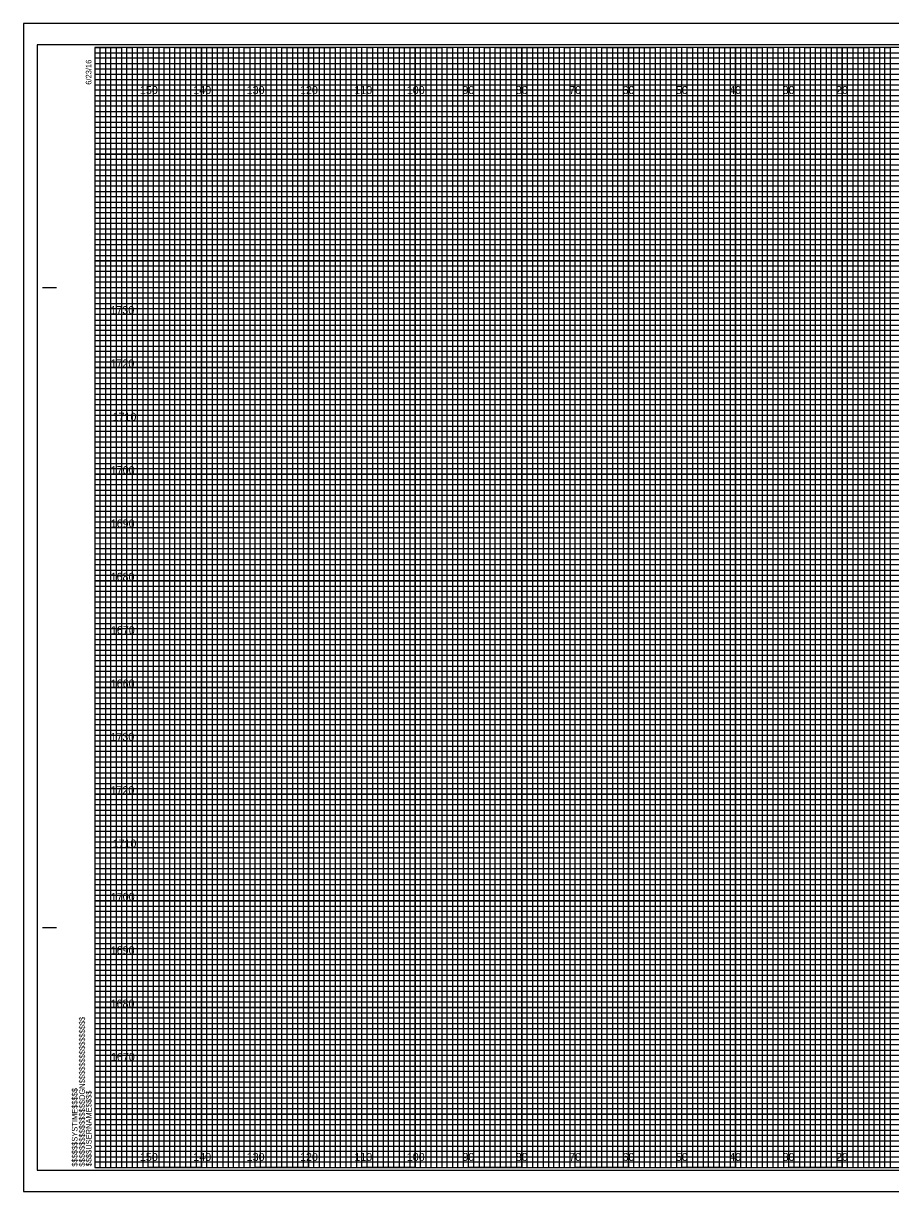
# Model space of a CAD drawing. Extents: x -13 to 323, y -5 to 6154.
# Drawn here: x -13.4 to 149.1, y -4.5 to 214.5 of the extents above; entities that cross this region are included whole.
import ezdxf

# ---------------------------------------------------------------- set-up
doc = ezdxf.new("R2010")
doc.units = 0
for name, color, linetype in [('Prop Retaining Wall', 7, 'Continuous'), ('Prop XS Alignment Label', 7, 'Continuous'), ('Prop XS DDE', 7, 'Continuous'), ('Prop XS DDE Elevations', 7, 'Continuous'), ('Prop XS DDE Slope Text', 7, 'Continuous'), ('Prop XS Earthwork Shape', 7, 'Continuous'), ('Prop XS Elevation Labels', 7, 'Continuous'), ('Prop XS Station Labels', 7, 'Continuous'), ('Raster_Level_0', 7, 'Continuous'), ('Scratch_Level_3', 7, 'Continuous'), ('Sheet Cutting Line CELL', 7, 'Continuous')]:
    doc.layers.add(name, color=color, linetype=linetype)

msp = doc.modelspace()

# ---------------------------------------------------------------- linework, layer by layer
at = {"layer": 'Prop Retaining Wall'}
for p, q in [((0, 209), (260, 209)), ((260, 207.98), (0, 207.98)), ((0, 207.98), (0, 207)), ((0, 207), (260, 207)), ((260, 205.89), (0, 205.89)), ((0, 205.89), (0, 204)), ((0, 204), (320, 204))]:
    msp.add_line(p, q, dxfattribs=at)
for points in [[(0, 203), (270, 203), (320, 203), (320, 202), (0, 202)], [(0, 201), (320, 201), (320, 199), (0, 199)], [(0, 198), (320, 198), (320, 197), (0, 196.98)], [(0, 196), (320, 196), (320, 194), (0, 194)], [(0, 193), (320, 193), (320, 192), (0, 192)], [(0, 191), (320, 191), (320, 189), (0, 189)], [(0, 188), (320, 188), (320, 187), (0, 187)], [(0, 186), (320, 186), (320, 184), (0, 184)], [(0, 183), (320, 183), (320, 182), (0, 182)], [(0, 181), (320, 181), (320, 179), (0, 179)], [(0, 178), (320, 178), (320, 177), (0, 177)], [(0, 176), (320, 176), (320, 173.95), (320, 173), (320, 172), (0, 172)], [(0, 174), (320, 174), (320, 173), (0, 173)], [(0, 171), (320, 171), (320, 169), (0, 169.03)], [(0, 169.03), (320, 169), (320, 168), (0, 168)], [(0, 167), (320, 167), (320, 166), (0, 166)], [(0, 164), (320, 164), (320, 163), (0, 163)], [(0, 162), (320, 162), (320, 161), (0, 161)], [(-0.07, 158.89), (320, 158.89), (320, 157.88), (-0.07, 157.88)], [(0, 157), (320, 157), (320, 156), (0, 156)], [(0, 154), (320, 154), (320, 153), (0, 153)], [(0, 152), (320, 152), (320, 151), (0, 151)], [(0, 149), (320, 149), (320, 148), (0, 148)], [(0, 147), (320, 147), (320, 146), (0, 146)], [(0, 144), (320, 144), (320, 143), (0, 143)], [(0, 142), (320, 142), (320, 141), (0, 141)], [(0, 139), (320, 139), (319.99, 137.98), (0, 138)], [(0, 137), (320, 137), (320, 136), (0, 136)], [(0, 134), (320, 134), (320, 133), (0, 133)], [(0, 132), (320, 132), (320, 131), (0, 131)], [(0, 129), (320, 129), (320, 128), (0, 128)], [(0, 127), (320, 127), (320, 126), (0, 126)], [(0, 124), (320, 124), (320, 123), (0, 123)], [(0, 122), (320, 122), (320, 121), (0, 121)], [(0, 119), (320, 119), (320, 118), (0, 118)], [(0, 116.99), (320.07, 116.91), (320, 116), (0, 116)], [(0, 114), (320, 114), (320, 113), (0, 113)], [(0, 112), (320, 112), (320, 111), (0, 111)], [(0, 109), (320, 109), (320, 108), (0, 108)], [(0, 107), (320, 107), (320, 106), (0, 106)], [(0, 104), (320, 104), (320, 103), (0, 103)], [(0, 102), (320, 102), (320, 101), (0, 101)], [(0, 99), (320, 99), (320, 98), (0, 98)], [(0, 97), (320, 97), (320, 96), (0, 96)], [(0, 94), (320, 94), (320, 93), (0, 93)], [(0, 92), (320, 92), (320, 91), (0, 91)], [(0, 89), (320, 89), (320, 88), (0, 88)], [(0, 87), (320, 87), (320, 86), (0, 86)], [(0, 84), (320, 84), (320, 83), (0, 83)], [(0, 82), (320, 82), (320, 81), (0, 81)], [(0, 79), (320, 79), (319.99, 77.98), (0, 78)], [(0, 77), (320, 77), (320, 76), (0, 76)], [(0, 74), (320, 74), (320, 73), (0, 73)], [(0, 72), (320, 72), (320, 71), (0, 71)], [(0, 69), (320, 69), (320, 68), (0, 68)], [(0, 67), (320, 67), (320, 66), (0, 66)], [(0, 64), (320, 64), (320, 63), (0, 63)], [(0, 62), (320, 62), (320, 61), (0, 61)], [(0, 59), (320, 59), (320, 58), (0, 58)], [(0, 56.99), (320.07, 56.91), (320, 56), (0, 56)], [(0, 54), (320, 54), (320, 53), (0, 53)], [(0, 52), (320, 52), (320, 51), (0, 51)], [(0, 49), (320, 49), (320, 48), (0, 48)], [(0, 47), (320, 47), (320, 46), (0, 46)], [(0, 44), (320, 44), (320, 43), (0, 43)], [(0, 42), (320, 42), (320, 41), (0, 41)], [(0, 39), (320, 39), (320, 38), (0, 38)], [(0, 37), (320, 37), (320, 36), (0, 36)], [(0, 34), (320, 34), (320, 33), (0, 33)], [(0, 32), (320, 32), (320, 31), (0, 31)], [(0, 29), (320, 29), (320, 28), (0, 28)], [(0, 27), (320, 27), (320, 26), (0, 26)], [(0, 24), (320, 24), (320, 23), (0, 23)], [(0, 22), (320, 22), (320, 21), (0, 21)], [(0, 19), (320, 19), (320, 18), (0, 18)], [(0, 17), (320, 17), (320, 16), (0, 16)], [(0, 14), (320, 14), (320, 13), (0, 13)], [(0, 12), (320, 12), (320, 11), (0, 11)], [(0, 9), (320, 9), (320, 8), (0, 8)], [(0, 7), (320, 7), (320, 6), (0, 6)], [(0, 4), (320, 4), (320, 3), (0, 3)], [(0, 2), (320, 2), (320, 1), (0, 1)]]:
    msp.add_lwpolyline(points, dxfattribs=at)
at = {"layer": 'Prop XS Alignment Label'}
for p, q in [((-9.8, 165), (-7.3, 165)), ((-9.7, 165), (-7.2, 165)), ((-9.8, 45), (-7.3, 45)), ((-9.7, 45), (-7.2, 45)), ((0, 0), (0, 0)), ((0, 0), (0, 0)), ((0, 0), (0, 0)), ((0, 0), (0, 0)), ((0, 0), (0, 0)), ((0, 0), (0, 0)), ((0, 0), (0, 0))]:
    msp.add_line(p, q, dxfattribs=at)
msp.add_lwpolyline([(320, 210), (0, 210), (0, 0), (320, 0)], close=True, dxfattribs=at)
at = {"layer": 'Prop XS DDE'}
msp.add_lwpolyline([(-13.4, -4.5), (323.3, -4.5), (323.3, 214.5), (-13.4, 214.5)], close=True, dxfattribs=at)
at = {"layer": 'Prop XS DDE Elevations'}
for p, q in [((10, 0), (10, 210)), ((20, 0), (20, 210)), ((30, 0), (30, 210)), ((40, 0), (40, 210)), ((50, 0), (50, 210)), ((60, 0), (60, 210)), ((70, 0), (70, 210)), ((80, 0), (80, 210)), ((90, 0), (90, 210)), ((100, 0), (100, 210)), ((110, 0), (110, 210)), ((120, 0), (120, 210)), ((130, 0), (130, 210)), ((140, 0), (140, 210)), ((0, 200), (320, 200)), ((0, 190), (320, 190)), ((0, 180), (320, 180)), ((0, 170), (320, 170)), ((0, 160), (320, 160)), ((0, 150), (320, 150)), ((0, 140), (320, 140)), ((0, 130), (320, 130)), ((0, 120), (320, 120)), ((0, 110), (320, 110)), ((0, 100), (320, 100)), ((0, 90), (320, 90)), ((0, 80), (320, 80)), ((0, 70), (320, 70)), ((0, 60), (320, 60)), ((0, 50), (320, 50)), ((0, 40), (320, 40)), ((0, 30), (320, 30)), ((0, 20), (320, 20)), ((0, 10), (320, 10))]:
    msp.add_line(p, q, dxfattribs=at)
at = {"layer": 'Prop XS DDE Slope Text'}
msp.add_lwpolyline([(-10.8, -0.5), (322.4, -0.5), (322.4, 210.5), (-10.8, 210.5)], close=True, dxfattribs=at)
at = {"layer": 'Prop XS Earthwork Shape'}
for p, q in [((10, 210), (0, 210)), ((10, 0), (10, 210)), ((30, 210), (20, 210)), ((20, 210), (20, 0)), ((30, 0), (30, 210)), ((50, 210), (40, 210)), ((40, 210), (40, 0)), ((50, 0), (50, 210)), ((70, 210), (60, 210)), ((60, 210), (60, 0)), ((70, 0), (70, 210)), ((90, 210), (80, 210)), ((80, 210), (80, 0)), ((90, 0), (90, 210)), ((110, 210), (100, 210)), ((100, 210), (100, 0)), ((110, 0), (110, 210)), ((130, 210), (120, 210)), ((120, 210), (120, 0)), ((130, 0), (130, 210)), ((150, 210), (140, 210)), ((140, 210), (140, 0)), ((20, 0), (10, 0)), ((40, 0), (30, 0)), ((60, 0), (50, 0)), ((80, 0), (70, 0)), ((100, 0), (90, 0)), ((120, 0), (110, 0)), ((140, 0), (130, 0))]:
    msp.add_line(p, q, dxfattribs=at)
for points in [[(0, 200), (320, 200), (320, 190), (0, 190)], [(0, 180), (320, 180), (320, 170), (0, 170)], [(0, 160), (320, 160), (320, 150), (0, 150)], [(0, 140), (320, 140), (320, 130), (0, 130)], [(0, 120), (320, 120), (320, 110), (0, 110)], [(0, 100), (320, 100), (320, 90), (0, 90)], [(0, 80), (320, 80), (320, 70), (0, 70)], [(0, 60), (320, 60), (320, 50), (0, 50)], [(0, 40), (320, 40), (320, 30), (0, 30)], [(0, 20), (320, 20), (320, 10), (0, 10)]]:
    msp.add_lwpolyline(points, dxfattribs=at)
at = {"layer": 'Prop XS Elevation Labels'}
for points in [[(0, 0), (1, 0), (1, 210), (2, 210), (2, 0)], [(2, 0), (3, 0), (3, 210), (4, 210), (4, 0)], [(5, 0), (6, 0), (6, 210), (7, 210), (7, 0)], [(7, 0), (8, 0), (8, 210), (9, 210), (9, 0)], [(10, 0), (11, 0), (11, 210), (12, 210), (12, 0)], [(12, 0), (13, 0), (13, 210), (14, 210), (14, 0)], [(15, 0), (16, 0), (16, 210), (17, 210), (17, 0)], [(17, 0), (18, 0), (18, 210), (19, 210), (19, 0)], [(20, 0), (21, 0), (21, 210), (22, 210), (22, 0)], [(22, 0), (23, 0), (23, 210), (24, 210), (24, 0)], [(25, 0), (26, 0), (26, 210), (27, 210), (27, 0)], [(27, 0), (28, 0), (28, 210), (29, 210), (29, 0)], [(30, 0), (31, 0), (31, 210), (32, 210), (32, 0)], [(32, 0), (33, 0), (33, 210), (34, 210), (34, 0)], [(35, 0), (36, 0), (36, 210), (37, 210), (37, 0)], [(37, 0), (38, 0), (38, 210), (39, 210), (39, 0)], [(40, 0), (41, 0), (41, 210), (42, 210), (42, 0)], [(42, 0), (43, 0), (43, 210), (44, 210), (44, 0)], [(45, 0), (46, 0), (46, 210), (47, 210), (47, 0)], [(47, 0), (48, 0), (48, 210), (49, 210), (49, 0)], [(50, 0), (51, 0), (51, 210), (52, 210), (52, 0)], [(52, 0), (53, 0), (53, 210), (54, 210), (54, 0)], [(55, 0), (56, 0), (56, 210), (57, 210), (57, 0)], [(57, 0), (58, 0), (58, 210), (59, 210), (59, 0)], [(60, 0), (61, 0), (61, 210), (62, 210), (62, 0)], [(62, 0), (63, 0), (63, 210), (64, 210), (64, 0)], [(65, 0), (66, 0), (66, 210), (67, 210), (67, 0)], [(67, 0), (68, 0), (68, 210), (69, 210), (69, 0)], [(70, 0), (71, 0), (71, 210), (72, 210), (72, 0)], [(72, 0), (73, 0), (73, 210), (74, 210), (74, 0)], [(75, 0), (76, 0), (76, 210), (77, 210), (77, 0)], [(77, 0), (78, 0), (78, 210), (79, 210), (79, 0)], [(80, 0), (81, 0), (81, 210), (82, 210), (82, 0)], [(82, 0), (83, 0), (83, 210), (84, 210), (84, 0)], [(85, 0), (86, 0), (86, 210), (87, 210), (87, 0)], [(87, 0), (88, 0), (88, 210), (89, 210), (89, 0)], [(90, 0), (91, 0), (91, 210), (92, 210), (92, 0)], [(92, 0), (93, 0), (93, 210), (94, 210), (94, 0)], [(95, 0), (96, 0), (96, 210), (97, 210), (97, 0)], [(97, 0), (98, 0), (98, 210), (99, 210), (99, 0)], [(100, 0), (101, 0), (101, 210), (102, 210), (102, 0)], [(102, 0), (103, 0), (103, 210), (104, 210), (104, 0)], [(105, 0), (106, 0), (106, 210), (107, 210), (107, 0)], [(107, 0), (108, 0), (108, 210), (109, 210), (109, 0)], [(110, 0), (111, 0), (111, 210), (112, 210), (112, 0)], [(112, 0), (113, 0), (113, 210), (114, 210), (114, 0)], [(115, 0), (116, 0), (116, 210), (117, 210), (117, 0)], [(117, 0), (118, 0), (118, 210), (119, 210), (119, 0)], [(120, 0), (121, 0), (121, 210), (122, 210), (122, 0)], [(122, 0), (123, 0), (123, 210), (124, 210), (124, 0)], [(125, 0), (126, 0), (126, 210), (127, 210), (127, 0)], [(127, 0), (128, 0), (128, 210), (129, 210), (129, 0)], [(130, 0), (131, 0), (131, 210), (132, 210), (132, 0)], [(132, 0), (133, 0), (133, 210), (134, 210), (134, 0)], [(135, 0), (136, 0), (136, 210), (137, 210), (137, 0)], [(137, 0), (138, 0), (138, 210), (139, 210), (139, 0)], [(140, 0), (141, 0), (141, 210), (142, 210), (142, 0)], [(142, 0), (143, 0), (143, 210), (144, 210), (144, 0)], [(145, 0), (146, 0), (146, 210), (147, 210), (147, 0)], [(147, 0), (148, 0), (148, 210), (149, 210), (149, 0)]]:
    msp.add_lwpolyline(points, dxfattribs=at)
at = {"layer": 'Prop XS Station Labels'}
for points in [[(0, 210), (5, 210), (5, 0), (15, 0), (15, 210), (25, 210), (25, 0), (35, 0), (35, 210), (45, 210), (45, 0), (55, 0), (55, 210), (65, 210), (65, 0), (75, 0), (75, 210), (85, 210), (85, 0), (95, 0), (95, 210), (105, 210), (105, 0), (115, 0), (115, 210), (125, 210), (125, 0), (135, 0), (135, 210), (145, 210), (145, 0), (155, 0)], [(0, 205), (275, 205)], [(0, 185), (320, 185), (320, 195), (0, 195)], [(0, 165), (320, 165), (320, 175), (0, 175)], [(0, 145), (320, 145), (320, 155), (0, 155)], [(0, 125), (320, 125), (320, 135), (0, 135)], [(0, 105), (320, 105), (320, 115), (0, 115)], [(0, 85), (320, 85), (320, 95), (0, 95)], [(0, 65), (320, 65), (320, 75), (0, 75)], [(0, 45), (320, 45), (320, 55), (0, 55)], [(0, 25), (320, 25), (320, 35), (0, 35)], [(0, 5), (320, 5), (320, 15), (0, 15)]]:
    msp.add_lwpolyline(points, dxfattribs=at)
at = {"layer": 'Sheet Cutting Line CELL'}
for p, q in [((323.3, 214.5), (-13.4, 214.5)), ((-13.4, 214.5), (-13.4, -4.5)), ((-13.4, -4.5), (323.3, -4.5))]:
    msp.add_line(p, q, dxfattribs=at)

# ---------------------------------------------------------------- texts
at = {"layer": 'Prop XS Alignment Label'}
for s, p in [('6/23/16', (-0.65, 203)), ('$$$$$$$$$$$$$$$$DGN$$$$$$$$$$$$$$$$', (-1.88, 0.18)), ('$$$$$$SYSTIME$$$$$', (-3.26, 0.18)), ('$$$$USERNAME$$$$', (-0.62, 0.23))]:
    msp.add_text(s, height=1.05, rotation=90, dxfattribs=at).set_placement(p)
at = {"layer": 'Raster_Level_0'}
for s, p in [('150', (8.44, 201.25)), ('140', (18.44, 201.25)), ('130', (28.44, 201.25)), ('120', (38.44, 201.25)), ('110', (48.62, 201.25)), ('100', (58.44, 201.25)), ('90', (68.86, 201.25)), ('80', (78.86, 201.25)), ('70', (88.86, 201.25)), ('60', (98.86, 201.25)), ('50', (108.86, 201.25)), ('40', (118.86, 201.25)), ('30', (128.86, 201.25)), ('20', (138.86, 201.25)), ('150', (8.44, 1.25)), ('140', (18.44, 1.25)), ('130', (28.44, 1.25)), ('120', (38.44, 1.25)), ('110', (48.62, 1.25)), ('100', (58.44, 1.25)), ('90', (68.86, 1.25)), ('80', (78.86, 1.25)), ('70', (88.86, 1.25)), ('60', (98.86, 1.25)), ('50', (108.86, 1.25)), ('40', (118.86, 1.25)), ('30', (128.86, 1.25)), ('20', (138.86, 1.25))]:
    msp.add_text(s, height=1.5, dxfattribs=at).set_placement(p)
at = {"layer": 'Scratch_Level_3'}
for s, p in [('1730', (2.92, 160)), ('1720', (2.93, 150)), ('1710', (3.31, 140)), ('1700', (2.98, 130)), ('1690', (2.97, 120)), ('1680', (2.95, 110)), ('1670', (3, 100)), ('1660', (2.97, 90)), ('1730', (2.92, 80)), ('1720', (2.93, 70)), ('1710', (3.31, 60)), ('1700', (2.98, 50)), ('1690', (2.97, 40)), ('1680', (2.95, 30)), ('1670', (3, 20))]:
    msp.add_text(s, height=1.5, dxfattribs=at).set_placement(p)

doc.saveas('drawing.dxf')
